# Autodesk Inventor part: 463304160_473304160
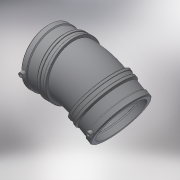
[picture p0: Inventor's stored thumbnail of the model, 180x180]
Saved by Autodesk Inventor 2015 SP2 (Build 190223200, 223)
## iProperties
Created: 2017-06
Part Number: 463304160_473304160
Material: Generic
Description: PLASSON 30° LIGHTFIT ELBOW 160
Document SubType Name: Modeling
Designer: KIM
Mass: 12693.1 g
Surface Area: 10598.3 cm^2
Volume: 12693.1 cm^3
Density: 1 g/cm^3
Appearance: Default
Author: KIM
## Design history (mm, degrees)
derived "46330.ipt"
feature "Solid1::46330.ipt"
tag "TaggingFeature1"
body "Solid1"
other parameters: "d14" = 17.6296, "d19" = 3.52592, "d20" = 168 deg, "d22" = 189.14, "d23" = 193, "d24" = 183.4658, "d25" = 135 deg, "d29" = 106, "d43" = 135 deg, "d45" = 12, "d47" = 9, "d48" = 189.14, "d49" = 193, "d50" = 0.965, "d51" = 94.57, "d52" = 150 deg, "d54" = 21.56, "d55" = 88.2, "d56" = 152, "d57" = 58.8, "d58" = 106, "d59" = 15, "d61" = 5 deg, "d63" = 4, "d64" = 14, "d65" = 0, "d67" = 150 deg, "d69" = 176, "d71" = 98, "d72" = 0, "d73" = 98, "d74" = 0, "d75" = 3, "d76" = 0, "L_1" = 98, "D_" = 193, "A_" = 106, "d_2" = 12
